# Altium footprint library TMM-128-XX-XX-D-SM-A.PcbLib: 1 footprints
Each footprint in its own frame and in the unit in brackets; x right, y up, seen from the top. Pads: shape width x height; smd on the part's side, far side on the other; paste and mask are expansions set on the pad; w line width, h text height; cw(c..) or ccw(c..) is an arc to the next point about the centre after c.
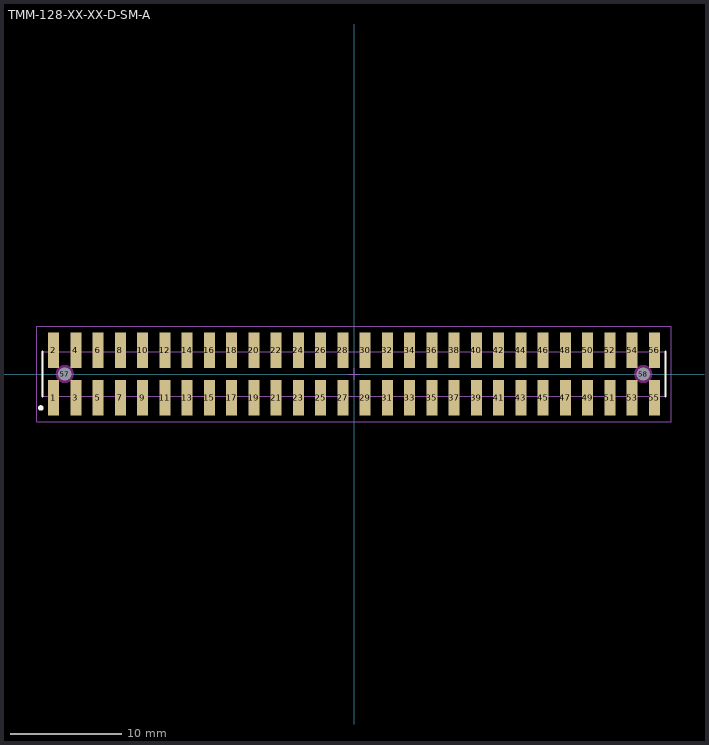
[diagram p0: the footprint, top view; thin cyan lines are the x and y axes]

## TMM-128-XX-XX-D-SM-A [mm] "2.00mm pitch, 56 pin, terminal strip; double row, w/alignment pins, SMT"
height 2.77
pads (58):
  rect 1x3.2 smd mask+0: 1(-27,-2.15) 2(-27,2.15) 3(-25,-2.15) 4(-25,2.15) 5(-23,-2.15) 6(-23,2.15) 7(-21,-2.15) 8(-21,2.15) 9(-19,-2.15) 10(-19,2.15) 11(-17,-2.15) 12(-17,2.15) 13(-15,-2.15) 14(-15,2.15) 15(-13,-2.15) 16(-13,2.15) 17(-11,-2.15) 18(-11,2.15) 19(-9,-2.15) 20(-9,2.15) 21(-7,-2.15) 22(-7,2.15) 23(-5,-2.15) 24(-5,2.15) 25(-3,-2.15) 26(-3,2.15) 27(-1,-2.15) 28(-1,2.15) 29(1,-2.15) 30(1,2.15) 31(3,-2.15) 32(3,2.15) 33(5,-2.15) 34(5,2.15) 35(7,-2.15) 36(7,2.15) 37(9,-2.15) 38(9,2.15) 39(11,-2.15) 40(11,2.15) 41(13,-2.15) 42(13,2.15) 43(15,-2.15) 44(15,2.15) 45(17,-2.15) 46(17,2.15) 47(19,-2.15) 48(19,2.15) 49(21,-2.15) 50(21,2.15) 51(23,-2.15) 52(23,2.15) 53(25,-2.15) 54(25,2.15) 55(27,-2.15) 56(27,2.15)
  round 1 hole 1.2 unplated mask+0: 57(-26,0) 58(26,0)
Top Overlay:
  circle w0.25: c-28.15,-3.05 r0.125
  lines w0.2: -28,-2 -28,2 ; 28,-2 28,2
Keep-Out Layer:
  pour cut-out: -25.193,0 -25.22,0.209 -25.301,0.403 -25.429,0.571 -25.596,0.699 -25.791,0.779 -26,0.807 -26.209,0.779 -26.403,0.699 -26.57,0.571 -26.699,0.403 -26.779,0.209 -26.807,0 -26.779,-0.209 -26.699,-0.403 -26.57,-0.571 -26.403,-0.699 -26.209,-0.779 -26,-0.807 -25.791,-0.779 -25.596,-0.699 -25.429,-0.571 -25.301,-0.403 -25.22,-0.209
  pour cut-out: 26.807,0 26.779,0.209 26.699,0.403 26.57,0.571 26.403,0.699 26.209,0.779 26,0.807 25.791,0.779 25.596,0.699 25.429,0.571 25.301,0.403 25.22,0.209 25.193,0 25.22,-0.209 25.301,-0.403 25.429,-0.571 25.596,-0.699 25.791,-0.779 26,-0.807 26.209,-0.779 26.403,-0.699 26.57,-0.571 26.699,-0.403 26.779,-0.209
Mechanical 12:
  lines w0.001: -28,-2 28,-2 28,2 -28,2 -28,-2
Mechanical 13:
  lines w0.1: -28,-2 28,-2 28,2 -28,2 -28,-2
  text ".Designator" at 0,-0.127 h1.52
Mechanical 15:
  lines w0.05: -0.5,0 0.5,0 ; 0,-0.5 0,0.5 ; -28.5,-4.3 28.5,-4.3 28.5,4.3 -28.5,4.3 -28.5,-4.3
